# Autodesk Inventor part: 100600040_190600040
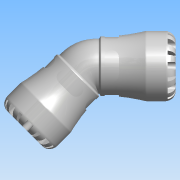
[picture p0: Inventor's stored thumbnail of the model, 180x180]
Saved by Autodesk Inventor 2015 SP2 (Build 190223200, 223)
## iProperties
Created: 2016-12
Part Number: 100600040_190600040
Material: PVC-Piping
Description: PLASSON 45° ELBOW 40-40 SERIES 1
Document SubType Name: Modeling
Designer: KIM
Mass: 664.223 g
Surface Area: 733.008 cm^2
Volume: 474.445 cm^3
Density: 1.4 g/cm^3
Appearance: Smooth - White
Author: KIM
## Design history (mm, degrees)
derived "1006.ipt"
feature "Solid1::1006.ipt"
tag "TaggingFeature1"
body "Solid1"
other parameters: "d1" = 29.82, "d8" = 59.5, "d13" = 8, "d14" = 8, "d15" = 0, "d17" = 360 deg, "d19" = 8 deg, "d20" = 0.8, "d21" = 0.8, "d22" = 8 deg, "d24" = 0, "d26" = 360 deg, "d33" = 7, "d43" = 54.6, "d51" = 0.7, "d54" = 14, "d55" = 8.8, "d57" = 15.68, "d58" = 0, "d74" = 0, "d77" = 3.33333, "d78" = 71, "d82" = 0.8, "d115" = 360 deg, "d207" = 90 deg, "d228" = 11.9, "d247" = 1.4, "d248" = 4.26, "d268" = 12.495, "d269" = 3.7485, "d270" = 88, "d277" = 135 deg, "d279" = 3.7485, "d280" = 135 deg, "d281" = 0, "d282" = 0, "l_" = 71, "A_" = 88, "d9" = 10
